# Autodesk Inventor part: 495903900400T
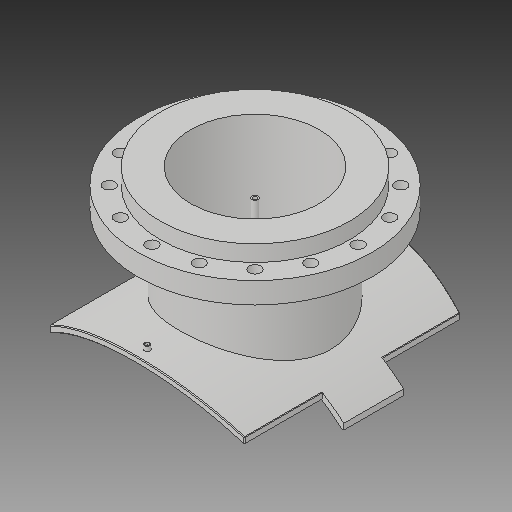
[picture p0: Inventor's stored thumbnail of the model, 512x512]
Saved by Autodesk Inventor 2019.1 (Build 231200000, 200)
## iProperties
Created: 2017-10
Part Number: 495903900400T
Material: Generic
Description: PLASSON FLANGED BRANCH SADDLE 900X400
Document SubType Name: Modeling
Designer: KIM
Mass: 2339.99 g
Surface Area: 3251.55 cm^2
Volume: 2339.99 cm^3
Density: 1 g/cm^3
Appearance: Default
Author: KIM
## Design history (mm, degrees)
derived "495904_495903.ipt"
feature "Solid1::495904_495903.ipt"
feature "Solid2::495904_495903.ipt"
tag "TaggingFeature1"
body "Solid1"
other parameters: "d1" = 15, "d2" = 495, "d4" = 0, "d6" = 152.5, "d7" = 0, "d12" = 475.6, "d13" = 14, "d14" = 274.5, "d16" = 5 deg, "d18" = 4, "d19" = 14, "d20" = 0, "d21" = 3, "d22" = 0, "d23" = 745, "d36" = 274.5, "d38" = 0, "d39" = 2, "d41" = 327, "d42" = 482, "d43" = 595, "d44" = 224, "d46" = 385.6, "d47" = 16, "d48" = 10.4, "d49" = 196, "d51" = 918, "d53" = 0, "d55" = 262.5, "d57" = 0, "d59" = 360 deg, "d61" = 54, "d63" = 0, "d67" = 15, "d70" = 0, "d71" = 2, "d_1" = 482, "x_" = 15, "D_" = 16, "DN_" = 327, "D_1" = 595, "t_" = 54, "Dp_" = 525
